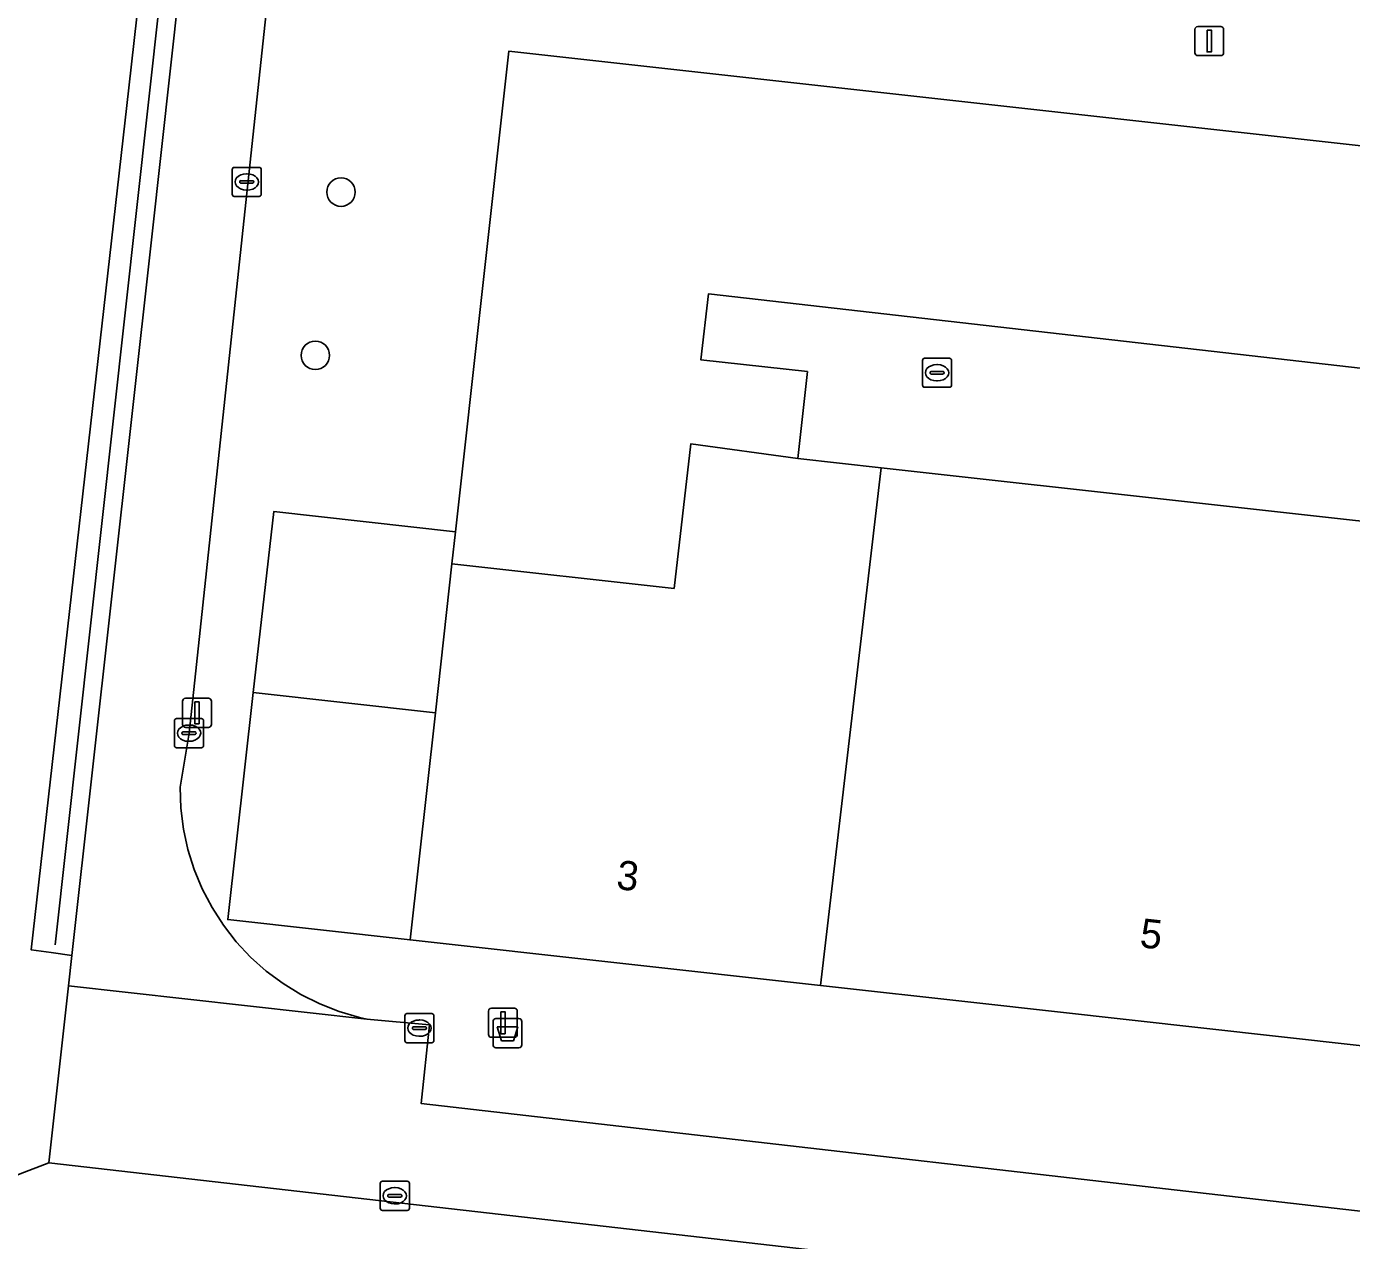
# Model space of a CAD drawing. Extents: x 162510 to 163918, y 388494 to 389774.
# Drawn here: x 162778.56 to 162824.04, y 388715.54 to 388757.22 of the extents above; entities that cross this region are included whole.
import ezdxf

# ---------------------------------------------------------------- set-up
doc = ezdxf.new("R2010")
doc.units = 0
for name, color, linetype in [('IMGEO_Afvalbak', 7, 'Continuous'), ('IMGEO_Boom', 7, 'Continuous'), ('IMGEO_Groenvoorziening', 7, 'Continuous'), ('IMGEO_Hek', 7, 'Continuous'), ('IMGEO_Kolk', 7, 'Continuous'), ('IMGEO_Lichtmast', 7, 'Continuous'), ('IMGEO_Pand', 7, 'Continuous'), ('IMGEO_Pand_nummerreeks', 7, 'Continuous'), ('IMGEO_Voetpad_open', 7, 'Continuous')]:
    doc.layers.add(name, color=color, linetype=linetype)

msp = doc.modelspace()

# ---------------------------------------------------------------- linework, layer by layer
at = {"layer": 'IMGEO_Afvalbak'}
for p, q in [((162794.676, 388723.161), (162795.466, 388723.161)), ((162795.466, 388723.161), (162794.676, 388723.161)), ((162794.576, 388722.261), (162794.576, 388723.061)), ((162794.576, 388723.061), (162794.576, 388722.261)), ((162795.566, 388723.061), (162795.566, 388722.261)), ((162795.566, 388722.261), (162795.566, 388723.061)), ((162795.466, 388722.161), (162794.676, 388722.161)), ((162794.676, 388722.161), (162795.466, 388722.161))]:
    msp.add_line(p, q, dxfattribs=at)
msp.add_lwpolyline([(162794.719, 388722.875), (162795.423, 388722.875), (162795.274, 388722.405), (162794.868, 388722.405), (162794.719, 388722.875)], dxfattribs=at)
for centre, start, end in [((162794.676, 388723.061), 90, 180), ((162794.676, 388723.061), 90, 180), ((162795.466, 388723.061), 0, 90), ((162795.466, 388723.061), 360, 90), ((162794.676, 388722.261), 180, 270), ((162794.676, 388722.261), 180, 270), ((162795.466, 388722.261), 270, 0), ((162795.466, 388722.261), 270, 0)]:
    msp.add_arc(centre, 0.1, start, end, dxfattribs=at)
at = {"layer": 'IMGEO_Boom'}
for centre in [(162789.357, 388751.535), (162788.475, 388745.931)]:
    msp.add_circle(centre, 0.489, dxfattribs=at)
at = {"layer": 'IMGEO_Groenvoorziening'}
msp.add_lwpolyline([(162693.788, 388721.694), (162698.73, 388720.407), (162703.528, 388719.715), (162703.809, 388719.674), (162705.509, 388719.489), (162706.051, 388723.761), (162774.678, 388716.282), (162777.249, 388717.372), (162778.349, 388717.838), (162779.329, 388718.213), (162780.004, 388724.284), (162780.12, 388725.328), (162779.405, 388725.427), (162778.724, 388725.521), (162782.069, 388755.112), (162782.886, 388762.34), (162784.221, 388762.216), (162784.238, 388762.364), (162788.481, 388799.816)], dxfattribs=at)
at = {"layer": 'IMGEO_Hek'}
msp.add_lwpolyline([(162783.538, 388761.764), (162779.548, 388725.694)], dxfattribs=at)
at = {"layer": 'IMGEO_Kolk'}
for p, q in [((162785.62, 388751.459), (162785.62, 388752.311)), ((162785.695, 388752.385), (162786.547, 388752.385)), ((162786.621, 388752.311), (162786.621, 388751.459)), ((162785.879, 388751.879), (162785.879, 388751.891)), ((162786.317, 388751.842), (162785.919, 388751.842)), ((162785.922, 388751.928), (162786.32, 388751.928)), ((162786.108, 388752.165), (162786.133, 388752.165)), ((162786.363, 388751.891), (162786.363, 388751.879)), ((162786.547, 388751.385), (162785.695, 388751.385)), ((162786.131, 388751.605), (162786.106, 388751.605)), ((162809.392, 388745.834), (162810.244, 388745.834)), ((162809.317, 388744.908), (162809.317, 388745.76)), ((162809.619, 388745.377), (162810.017, 388745.377)), ((162809.805, 388745.614), (162809.83, 388745.614)), ((162810.318, 388745.76), (162810.318, 388744.908)), ((162809.576, 388745.328), (162809.576, 388745.34)), ((162810.014, 388745.291), (162809.616, 388745.291)), ((162809.828, 388745.054), (162809.803, 388745.054)), ((162810.06, 388745.34), (162810.06, 388745.328)), ((162810.244, 388744.834), (162809.392, 388744.834)), ((162783.639, 388732.535), (162783.639, 388733.387)), ((162783.714, 388733.461), (162784.566, 388733.461)), ((162784.127, 388733.241), (162784.152, 388733.241)), ((162784.64, 388733.387), (162784.64, 388732.535)), ((162783.898, 388732.955), (162783.898, 388732.967)), ((162784.336, 388732.918), (162783.938, 388732.918)), ((162783.941, 388733.004), (162784.339, 388733.004)), ((162784.15, 388732.681), (162784.125, 388732.681)), ((162784.382, 388732.967), (162784.382, 388732.955)), ((162784.566, 388732.461), (162783.714, 388732.461)), ((162791.547, 388722.409), (162791.547, 388723.261)), ((162791.622, 388723.335), (162792.474, 388723.335)), ((162792.035, 388723.115), (162792.06, 388723.115)), ((162792.548, 388723.261), (162792.548, 388722.409)), ((162791.806, 388722.829), (162791.806, 388722.841)), ((162792.244, 388722.792), (162791.846, 388722.792)), ((162791.849, 388722.878), (162792.247, 388722.878)), ((162792.29, 388722.841), (162792.29, 388722.829)), ((162792.474, 388722.335), (162791.622, 388722.335)), ((162792.058, 388722.555), (162792.033, 388722.555)), ((162790.702, 388716.654), (162790.702, 388717.506)), ((162790.777, 388717.58), (162791.629, 388717.58)), ((162791.19, 388717.36), (162791.215, 388717.36)), ((162791.703, 388717.506), (162791.703, 388716.654)), ((162790.961, 388717.074), (162790.961, 388717.086)), ((162791.399, 388717.037), (162791.001, 388717.037)), ((162791.004, 388717.123), (162791.402, 388717.123)), ((162791.213, 388716.8), (162791.188, 388716.8)), ((162791.445, 388717.086), (162791.445, 388717.074)), ((162791.629, 388716.58), (162790.777, 388716.58))]:
    msp.add_line(p, q, dxfattribs=at)
for points in [[(162785.62, 388751.459), (162785.62, 388752.311)], [(162785.695, 388752.385), (162786.547, 388752.385)], [(162786.621, 388752.311), (162786.621, 388751.459)], [(162786.547, 388751.385), (162785.695, 388751.385)], [(162809.392, 388745.834), (162810.244, 388745.834)], [(162809.317, 388744.908), (162809.317, 388745.76)], [(162810.318, 388745.76), (162810.318, 388744.908)], [(162810.244, 388744.834), (162809.392, 388744.834)], [(162783.639, 388732.535), (162783.639, 388733.387)], [(162783.714, 388733.461), (162784.566, 388733.461)], [(162784.64, 388733.387), (162784.64, 388732.535)], [(162784.566, 388732.461), (162783.714, 388732.461)], [(162791.547, 388722.409), (162791.547, 388723.261)], [(162791.622, 388723.335), (162792.474, 388723.335)], [(162792.548, 388723.261), (162792.548, 388722.409)], [(162792.474, 388722.335), (162791.622, 388722.335)], [(162790.702, 388716.654), (162790.702, 388717.506)], [(162790.777, 388717.58), (162791.629, 388717.58)], [(162791.703, 388717.506), (162791.703, 388716.654)], [(162791.629, 388716.58), (162790.777, 388716.58)]]:
    msp.add_lwpolyline(points, dxfattribs=at)
for centre, radius, start, end in [((162785.697, 388752.309), 0.0765, 91.552, 178.448), ((162785.697, 388752.309), 0.0765, 91.552, 178.448), ((162786.545, 388752.309), 0.0765, 1.552, 88.448), ((162786.545, 388752.309), 0.0765, 1.552, 88.448), ((162785.919, 388751.888), 0.0403, 85.8775, 175.7526), ((162785.916, 388751.878), 0.0366, 178.938, 274.7102), ((162786.32, 388751.885), 0.043, 264.8664, 352.4533), ((162786.324, 388751.89), 0.0386, 1.7309, 96.639), ((162785.697, 388751.461), 0.0765, 181.552, 268.448), ((162785.697, 388751.461), 0.0765, 181.552, 268.448), ((162786.545, 388751.461), 0.0765, 271.552, 358.448), ((162786.545, 388751.461), 0.0765, 271.552, 358.448), ((162809.394, 388745.758), 0.0765, 91.552, 178.448), ((162809.394, 388745.758), 0.0765, 91.552, 178.448), ((162810.242, 388745.758), 0.0765, 1.552, 88.448), ((162810.242, 388745.758), 0.0765, 1.552, 88.448), ((162809.616, 388745.337), 0.0403, 85.8775, 175.7526), ((162810.021, 388745.339), 0.0386, 1.7309, 96.639), ((162809.394, 388744.91), 0.0765, 181.552, 268.448), ((162809.394, 388744.91), 0.0765, 181.552, 268.448), ((162809.613, 388745.327), 0.0366, 178.938, 274.7102), ((162810.017, 388745.334), 0.043, 264.8664, 352.4533), ((162810.242, 388744.91), 0.0765, 271.552, 358.448), ((162810.242, 388744.91), 0.0765, 271.552, 358.448), ((162783.716, 388733.385), 0.0765, 91.552, 178.448), ((162783.716, 388733.385), 0.0765, 91.552, 178.448), ((162784.564, 388733.385), 0.0765, 1.552, 88.448), ((162784.564, 388733.385), 0.0765, 1.552, 88.448), ((162783.938, 388732.964), 0.0403, 85.8775, 175.7526), ((162783.935, 388732.954), 0.0366, 178.938, 274.7102), ((162784.339, 388732.961), 0.043, 264.8664, 352.4533), ((162784.343, 388732.966), 0.0386, 1.7309, 96.639), ((162783.716, 388732.537), 0.0765, 181.552, 268.448), ((162783.716, 388732.537), 0.0765, 181.552, 268.448), ((162784.564, 388732.537), 0.0765, 271.552, 358.448), ((162784.564, 388732.537), 0.0765, 271.552, 358.448), ((162791.624, 388723.259), 0.0765, 91.552, 178.448), ((162791.624, 388723.259), 0.0765, 91.552, 178.448), ((162792.472, 388723.259), 0.0765, 1.552, 88.448), ((162792.472, 388723.259), 0.0765, 1.552, 88.448), ((162791.846, 388722.838), 0.0403, 85.8775, 175.7526), ((162791.843, 388722.828), 0.0366, 178.938, 274.7102), ((162792.247, 388722.835), 0.043, 264.8664, 352.4533), ((162792.251, 388722.84), 0.0386, 1.7309, 96.639), ((162791.624, 388722.411), 0.0765, 181.552, 268.448), ((162791.624, 388722.411), 0.0765, 181.552, 268.448), ((162792.472, 388722.411), 0.0765, 271.552, 358.448), ((162792.472, 388722.411), 0.0765, 271.552, 358.448), ((162790.779, 388717.504), 0.0765, 91.552, 178.448), ((162790.779, 388717.504), 0.0765, 91.552, 178.448), ((162791.627, 388717.504), 0.0765, 1.552, 88.448), ((162791.627, 388717.504), 0.0765, 1.552, 88.448), ((162791.001, 388717.083), 0.0403, 85.8775, 175.7526), ((162790.998, 388717.073), 0.0366, 178.938, 274.7102), ((162791.402, 388717.08), 0.043, 264.8664, 352.4533), ((162791.406, 388717.085), 0.0386, 1.7309, 96.639), ((162790.779, 388716.656), 0.0765, 181.552, 268.448), ((162790.779, 388716.656), 0.0765, 181.552, 268.448), ((162791.627, 388716.656), 0.0765, 271.552, 358.448), ((162791.627, 388716.656), 0.0765, 271.552, 358.448)]:
    msp.add_arc(centre, radius, start, end, dxfattribs=at)
for centre, major_axis, ratio, start_param, end_param in [((162786.107, 388751.885), (-0.387, 0.002), 0.722429, 4.712389, 7.853982), ((162786.132, 388751.885), (-0.39, 0.002), 0.717154, 1.570796, 4.712389), ((162809.804, 388745.334), (-0.387, 0.002), 0.722429, 4.712389, 7.853982), ((162809.829, 388745.334), (-0.39, 0.002), 0.717154, 1.570796, 4.712389), ((162784.126, 388732.961), (-0.387, 0.002), 0.722429, 4.712389, 7.853982), ((162784.151, 388732.961), (-0.39, 0.002), 0.717154, 1.570796, 4.712389), ((162792.034, 388722.835), (-0.387, 0.002), 0.722429, 4.712389, 7.853982), ((162792.059, 388722.835), (-0.39, 0.002), 0.717154, 1.570796, 4.712389), ((162791.189, 388717.08), (-0.387, 0.002), 0.722429, 4.712389, 7.853982), ((162791.214, 388717.08), (-0.39, 0.002), 0.717154, 1.570796, 4.712389)]:
    msp.add_ellipse(centre, major_axis=major_axis, ratio=ratio, start_param=start_param, end_param=end_param, dxfattribs=at)
at = {"layer": 'IMGEO_Lichtmast'}
for p, q in [((162818.766, 388757.221), (162819.556, 388757.221)), ((162819.556, 388757.221), (162818.766, 388757.221)), ((162818.666, 388756.321), (162818.666, 388757.121)), ((162818.666, 388757.121), (162818.666, 388756.321)), ((162819.656, 388757.121), (162819.656, 388756.321)), ((162819.656, 388756.321), (162819.656, 388757.121)), ((162819.556, 388756.221), (162818.766, 388756.221)), ((162818.766, 388756.221), (162819.556, 388756.221)), ((162783.917, 388733.259), (162783.917, 388734.059)), ((162783.917, 388734.059), (162783.917, 388733.259)), ((162784.017, 388734.159), (162784.807, 388734.159)), ((162784.807, 388734.159), (162784.017, 388734.159)), ((162784.907, 388734.059), (162784.907, 388733.259)), ((162784.907, 388733.259), (162784.907, 388734.059)), ((162784.807, 388733.159), (162784.017, 388733.159)), ((162784.017, 388733.159), (162784.807, 388733.159)), ((162794.519, 388723.52), (162795.309, 388723.52)), ((162795.309, 388723.52), (162794.519, 388723.52)), ((162794.419, 388722.62), (162794.419, 388723.42)), ((162794.419, 388723.42), (162794.419, 388722.62)), ((162795.409, 388723.42), (162795.409, 388722.62)), ((162795.409, 388722.62), (162795.409, 388723.42)), ((162795.309, 388722.52), (162794.519, 388722.52)), ((162794.519, 388722.52), (162795.309, 388722.52))]:
    msp.add_line(p, q, dxfattribs=at)
for points in [[(162819.086, 388757.096), (162819.236, 388757.096), (162819.236, 388756.346), (162819.086, 388756.346), (162819.086, 388757.096)], [(162784.337, 388734.034), (162784.487, 388734.034), (162784.487, 388733.284), (162784.337, 388733.284), (162784.337, 388734.034)], [(162794.839, 388723.395), (162794.989, 388723.395), (162794.989, 388722.645), (162794.839, 388722.645), (162794.839, 388723.395)]]:
    msp.add_lwpolyline(points, dxfattribs=at)
for centre, start, end in [((162818.766, 388757.121), 90, 180), ((162818.766, 388757.121), 90, 180), ((162819.556, 388757.121), 0, 90), ((162819.556, 388757.121), 360, 90), ((162818.766, 388756.321), 180, 270), ((162818.766, 388756.321), 180, 270), ((162819.556, 388756.321), 270, 0), ((162819.556, 388756.321), 270, 0), ((162784.017, 388734.059), 90, 180), ((162784.017, 388734.059), 90, 180), ((162784.807, 388734.059), 0, 90), ((162784.807, 388734.059), 360, 90), ((162784.017, 388733.259), 180, 270), ((162784.017, 388733.259), 180, 270), ((162784.807, 388733.259), 270, 0), ((162784.807, 388733.259), 270, 0), ((162794.519, 388723.42), 90, 180), ((162794.519, 388723.42), 90, 180), ((162795.309, 388723.42), 0, 90), ((162795.309, 388723.42), 360, 90), ((162794.519, 388722.62), 180, 270), ((162794.519, 388722.62), 180, 270), ((162795.309, 388722.62), 270, 0), ((162795.309, 388722.62), 270, 0)]:
    msp.add_arc(centre, 0.1, start, end, dxfattribs=at)
at = {"layer": 'IMGEO_Pand'}
for points in [[(162793.165, 388738.779), (162800.79, 388737.93), (162801.37, 388742.896), (162805.036, 388742.393), (162805.366, 388745.376), (162801.707, 388745.78), (162801.971, 388748.041), (162831.367, 388744.685), (162835.187, 388744.249), (162836.331, 388744.118), (162834.549, 388728.329), (162834.857, 388728.294), (162842.265, 388727.462), (162845.081, 388750.819), (162795.118, 388756.373), (162793.287, 388739.876)], [(162805.821, 388724.296), (162807.897, 388742.075), (162805.036, 388742.393), (162801.37, 388742.896), (162800.79, 388737.93), (162793.165, 388738.779), (162792.596, 388733.657), (162791.731, 388725.862)], [(162805.821, 388724.296), (162811.184, 388723.7), (162824.203, 388722.252), (162825.835, 388722.071), (162827.673, 388721.867), (162829.651, 388739.658), (162807.897, 388742.075)]]:
    msp.add_lwpolyline(points, close=True, dxfattribs=at)
at = {"layer": 'IMGEO_Voetpad_open'}
for points in [[(162784.139, 388761.491), (162784.221, 388762.216), (162782.886, 388762.34), (162782.069, 388755.112), (162778.724, 388725.521), (162779.405, 388725.427), (162780.12, 388725.328), (162782.862, 388750)], [(162801.971, 388748.041), (162801.707, 388745.78), (162805.366, 388745.376), (162805.036, 388742.393), (162807.897, 388742.075), (162829.651, 388739.658), (162830.811, 388739.588), (162831.367, 388744.685)], [(162787.046, 388740.569), (162786.346, 388734.36), (162792.596, 388733.657), (162793.165, 388738.779), (162793.287, 388739.876)], [(162786.346, 388734.36), (162785.467, 388726.559), (162791.731, 388725.862), (162792.596, 388733.657)]]:
    msp.add_lwpolyline(points, close=True, dxfattribs=at)
for points in [[(162784.139, 388761.491), (162782.862, 388750), (162780.12, 388725.328), (162780.004, 388724.284), (162790.244, 388723.146), (162789.99, 388723.203), (162789.299, 388723.404), (162788.627, 388723.666), (162787.982, 388723.987), (162787.368, 388724.364), (162786.791, 388724.794), (162786.254, 388725.275), (162785.762, 388725.801), (162785.319, 388726.369), (162784.929, 388726.975), (162784.594, 388727.613), (162784.317, 388728.278), (162784.102, 388728.965), (162783.948, 388729.669), (162783.858, 388730.384), (162783.832, 388731.104), (162784.14, 388732.957), (162785.965, 388750), (162787.054, 388760.164)], [(162787.054, 388760.164), (162785.965, 388750), (162784.14, 388732.957), (162783.832, 388731.104), (162783.858, 388730.384), (162783.948, 388729.669), (162784.102, 388728.965), (162784.317, 388728.278), (162784.594, 388727.613), (162784.929, 388726.975), (162785.319, 388726.369), (162785.762, 388725.801), (162786.254, 388725.275), (162786.791, 388724.794), (162787.368, 388724.364), (162787.982, 388723.987), (162788.627, 388723.666), (162789.299, 388723.404), (162789.99, 388723.203), (162790.244, 388723.146), (162792.398, 388722.946), (162792.106, 388720.253), (162827.047, 388716.24)], [(162824.203, 388722.252), (162811.184, 388723.7), (162805.821, 388724.296), (162791.731, 388725.862), (162785.467, 388726.559), (162786.346, 388734.36), (162787.046, 388740.569), (162793.287, 388739.876), (162795.118, 388756.373), (162845.081, 388750.819)], [(162827.047, 388716.24), (162792.106, 388720.253), (162792.398, 388722.946), (162790.244, 388723.146), (162780.004, 388724.284), (162779.329, 388718.213), (162822.4, 388713.295), (162822.606, 388713.269), (162823.334, 388713.136), (162824.046, 388712.938)], [(162824.046, 388712.938), (162823.334, 388713.136), (162822.606, 388713.269), (162822.4, 388713.295), (162779.329, 388718.213), (162778.349, 388717.838), (162777.249, 388717.372), (162774.678, 388716.282), (162706.051, 388723.761)]]:
    msp.add_lwpolyline(points, dxfattribs=at)

# ---------------------------------------------------------------- texts
at = {"layer": 'IMGEO_Pand_nummerreeks'}
for s, rotation, p in [('3', 353.658, (162798.78, 388727.614)), ('5', 353.6572, (162816.751, 388725.617))]:
    msp.add_text(s, height=1, rotation=rotation, dxfattribs=at).set_placement(p)

doc.saveas('drawing.dxf')
